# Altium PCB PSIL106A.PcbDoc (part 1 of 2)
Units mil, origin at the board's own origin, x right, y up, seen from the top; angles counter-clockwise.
Board outline 4000 x 3327 mil, 2 copper layers (Top Layer, Bottom Layer), stack 62 mil thick; 63 components, 23 nets, 108 pads, 247 vias.
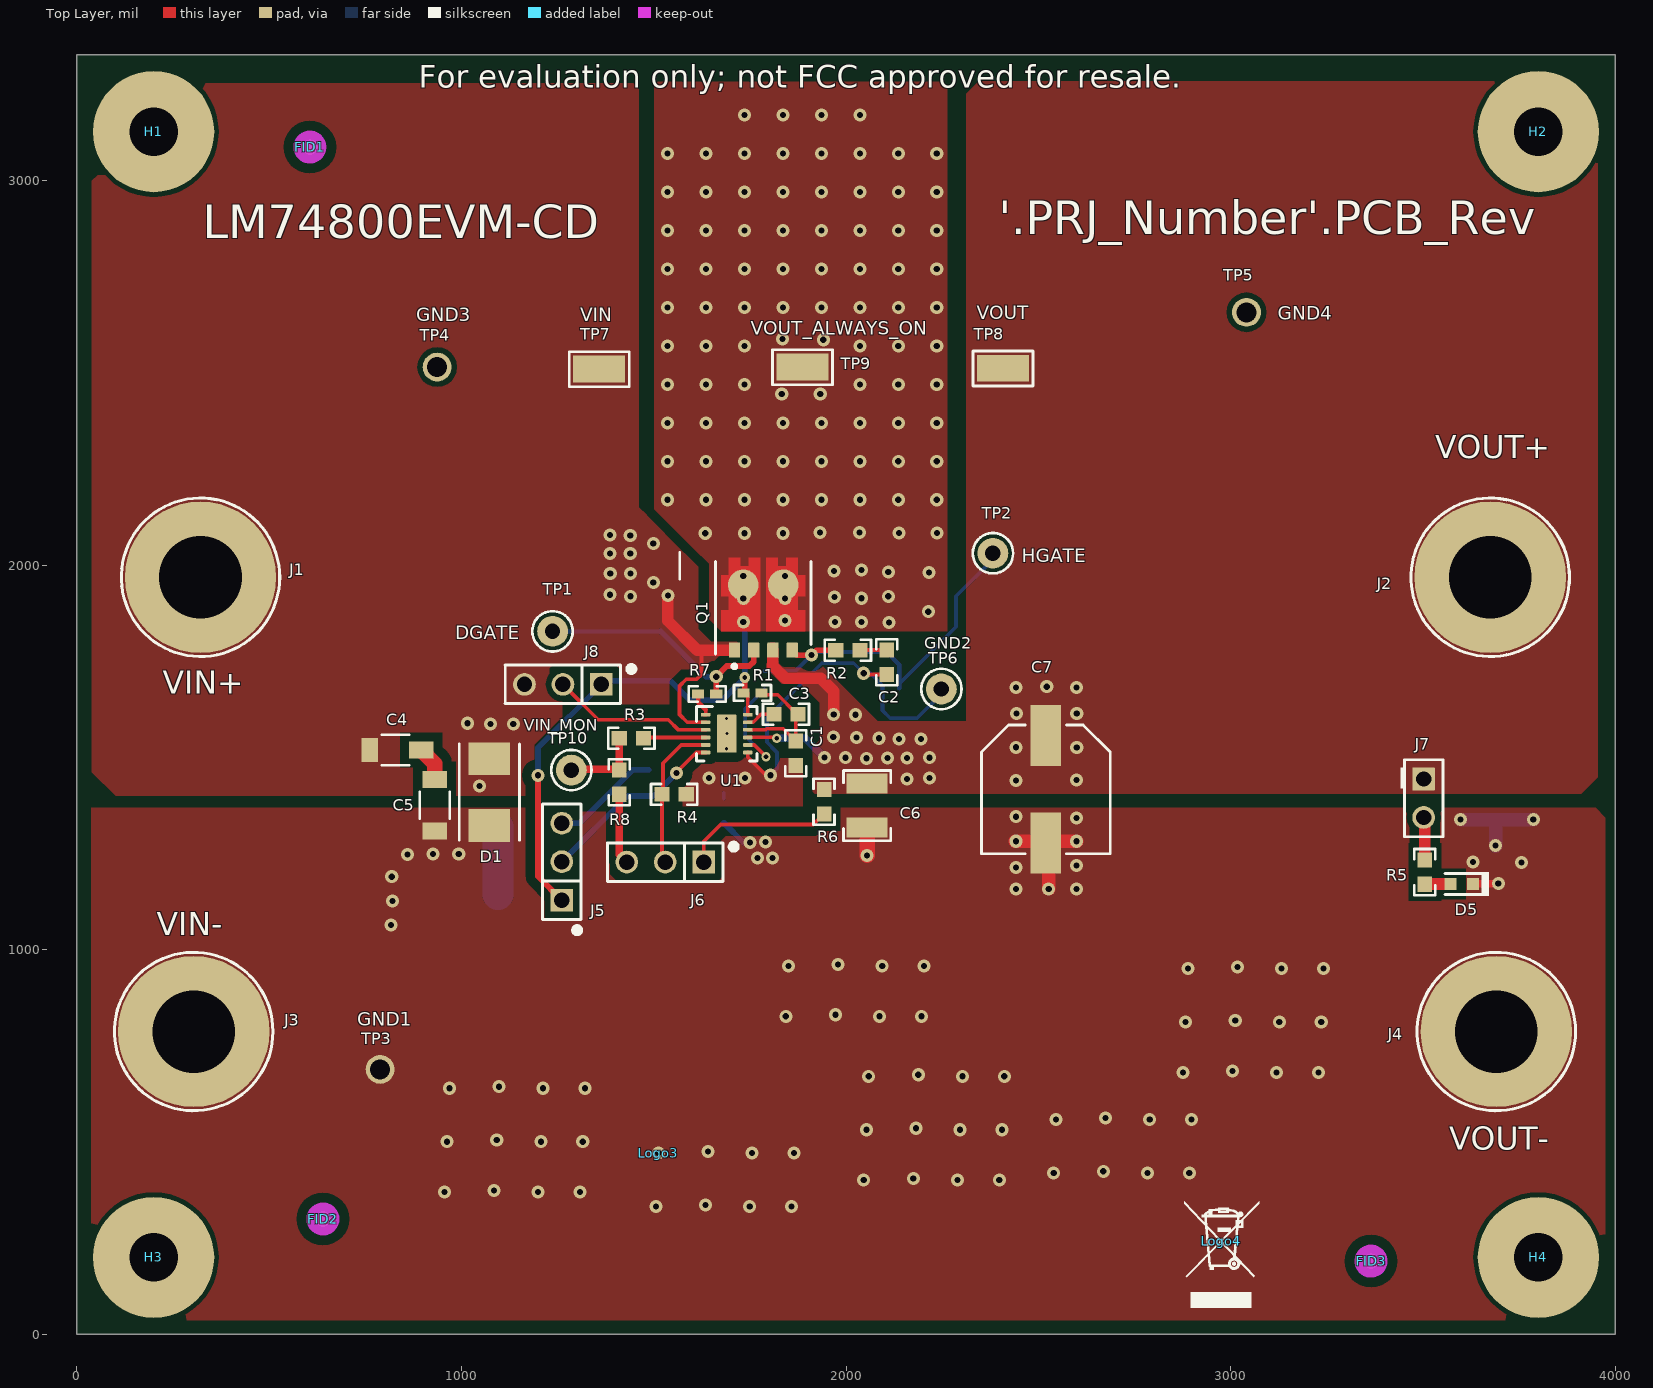
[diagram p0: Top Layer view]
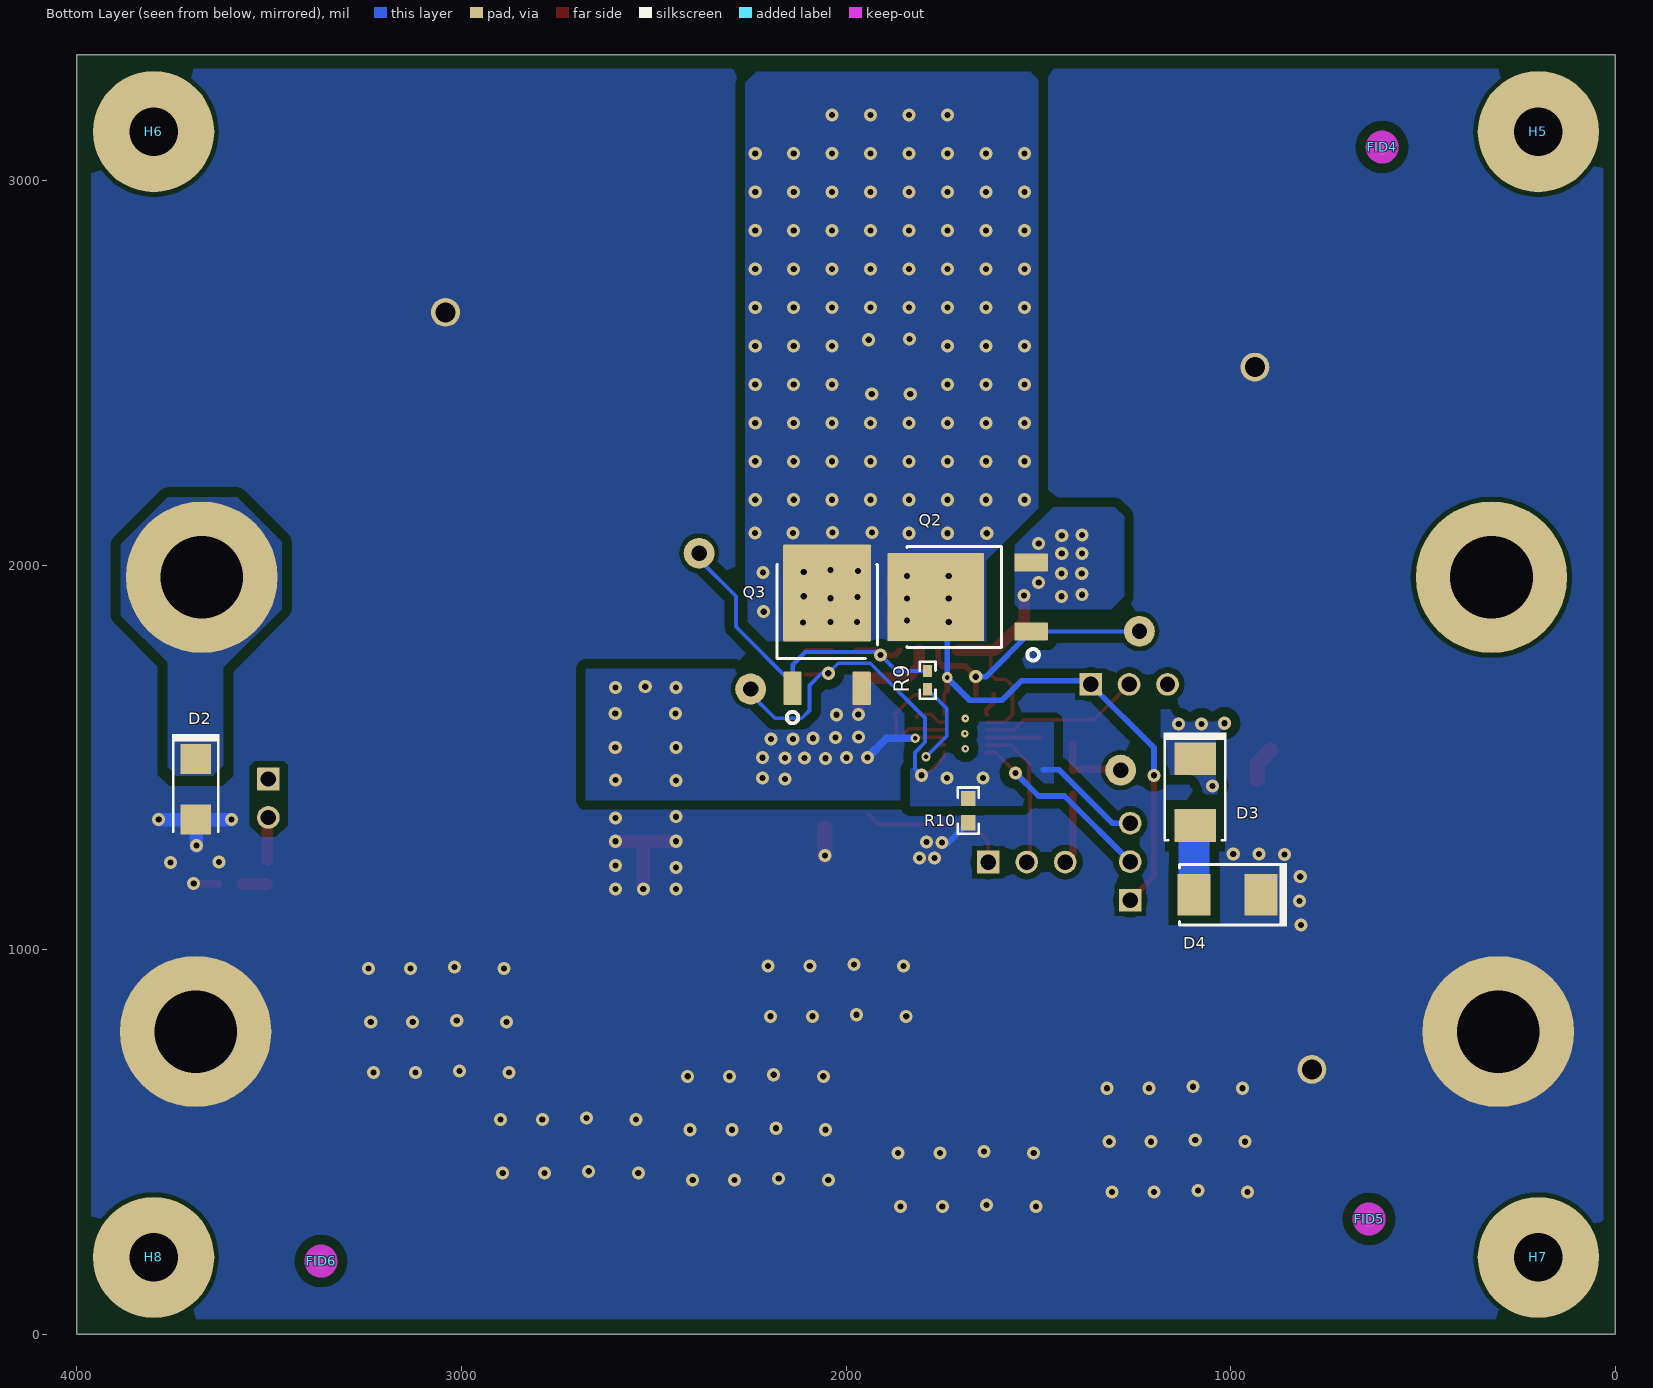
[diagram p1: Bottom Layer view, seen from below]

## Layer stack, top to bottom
Top Solder: solder mask 0.4, Solder Resist, Dk 3.5
Top Layer: signal copper 1.4
Dielectric1: core 59.2, FR-4 High Tg, Dk 4.8
Bottom Layer: signal copper 1.4
Bottom Solder: solder mask 0.4, Solder Resist, Dk 3.5

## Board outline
0,0 0,3327 4000,3327 4000,0

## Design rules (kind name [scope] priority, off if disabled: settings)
AcuteAngle [All] p1: minimum=4.50000000000000E+0001 checktracksonly=FALSE
AssemblyTestPointUsage [All] p1: valid=2
BoardOutlineClearance BoardOutlineClearance_MountingHoles [OnCopper and InComponentClass('Mounting Holes')] p1: gap=39.37 ignorepadtopadclearanceinfootprint=FALSE
BoardOutlineClearance BoardOutlineClearance_Poly [OnCopper and IsPoly] p2: gap=25 ignorepadtopadclearanceinfootprint=FALSE
BoardOutlineClearance [OnCopper and Not InComponentClass('Logo') and not InComponentClass('FiducialMark') and not InRegion(1000,500,4000,800) and not InPoly] p3: gap=75 ignorepadtopadclearanceinfootprint=FALSE
Clearance Clearance_Keepouts [((IsTrack Or IsArc) And Not InPoly) And IsFree and IsKeepOut vs ((IsTrack Or IsArc) And Not InPoly) And IsFree and IsKeepOut] p1: gap=0 ignorepadtopadclearanceinfootprint=FALSE
Clearance Clearance_Poly [InPolygon] p2: gap=25 ignorepadtopadclearanceinfootprint=TRUE except(12: THPad-Fill THPad-Poly THPad-Region)
Clearance Clearance_FiducialMark [IsKeepOut and InComponentClass('FiducialMark') vs IsPad and InComponentClass('FiducialMark')] p3: gap=0 ignorepadtopadclearanceinfootprint=FALSE
Clearance [All] p4: gap=8 ignorepadtopadclearanceinfootprint=TRUE except(20: Fill-Fill Fill-Poly Fill-Region Poly-Poly Poly-Region Region-Region)
ComponentClearance ComponentClearance_MountingHoles_FiducialMarks [InComponentClass('Mounting Holes') vs InComponentClass('FiducialMark')] p1: gap=50 collisioncheckmode=3 verticalgap=10 showdistances=FALSE
ComponentClearance ComponentClearance_Shunt [InComponentClass('Header') vs InComponentClass('Shunt')] p2: gap=0 collisioncheckmode=3 verticalgap=0 showdistances=FALSE
ComponentClearance ComponentClearance_Logo [InComponentClass('Logo')] p3: gap=50 collisioncheckmode=3 verticalgap=10 showdistances=FALSE
ComponentClearance ComponentClearance_ScrewToNut [(HasFootprint('NY PMS 440 0025 PH')) vs (HasFootprint('Keystone_1902C'))] p4: gap=5 collisioncheckmode=3 verticalgap=10 showdistances=FALSE
ComponentClearance ComponentClearance_MountingHoles [InComponentClass('Mounting Holes')] p5: gap=250 collisioncheckmode=3 verticalgap=100000 showdistances=FALSE
ComponentClearance ComponentClearance_SmallPassives [HasFootprint('0201*') or HasFootprint('0402*') or HasFootprint('0508') or HasFootprint('0603*') or HasFootprint('0612') or HasFootprint('0805*') or HasFootprint('0815*') or HasFootprint('0830*') or HasFootprint('1206*') or HasFootprint('1210*') or HasFootprint('1808*') or HasFootprint('1812*') or HasFootprint('1825*') or HasFootprint('2010*') or HasFootprint('2220*') or HasFootprint('2225*') or HasFootprint('2512*') or HasFootprint('2728*') or HasFootprint('3518*') vs HasFootprint('0201*') or HasFootprint('0402*') or HasFootprint('0508') or HasFootprint('0603*') or HasFootprint('0612') or HasFootprint('0805*') or HasFootprint('0815*') or HasFootprint('0830*') or HasFootprint('1206*') or HasFootprint('1210*') or HasFootprint('1808*') or HasFootprint('1812*') or HasFootprint('1825*') or HasFootprint('2010*') or HasFootprint('2220*') or HasFootprint('2225*') or HasFootprint('2512*') or HasFootprint('2728*') or HasFootprint('3518*')] p6: gap=14.96 collisioncheckmode=3 verticalgap=10 showdistances=FALSE
ComponentClearance ComponentClearance_THtoSMT [IsThruComponent vs IsSMTComponent] p7: gap=40 collisioncheckmode=3 verticalgap=30 showdistances=FALSE
ComponentClearance ComponentClearance_THtoTH [IsThruComponent vs IsThruComponent] p8: gap=30 collisioncheckmode=3 verticalgap=30 showdistances=FALSE
ComponentClearance [All] p9: gap=30 collisioncheckmode=3 verticalgap=10 showdistances=FALSE
DiffPairsRouting [All] p1: maxlimit=100 minlimit=10 mostfreqgap=10 toplayer_minwidth=15 toplayer_maxwidth=15 toplayer_prefwidth=15 bottomlayer_minwidth=15 bottomlayer_maxwidth=15 bottomlayer_prefwidth=15 substack1={53B530E0-F7B8-43D4-88A3-5FD2656F86AF} toplayer_{53b530e0-f7b8-43d4-88a3-5fd2656f86af}_minwidth=15 toplayer_{53b530e0-f7b8-43d4-88a3-5fd2656f86af}_maxwidth=15 toplayer_{53b530e0-f7b8-43d4-88a3-5fd2656f86af}_prefwidth=15 bottomlayer_{53b530e0-f7b8-43d4-88a3-5fd2656f86af}_minwidth=15 bottomlayer_{53b530e0-f7b8-43d4-88a3-5fd2656f86af}_maxwidth=15 bottomlayer_{53b530e0-f7b8-43d4-88a3-5fd2656f86af}_prefwidth=15 maxuncoupledlength=1000
FabricationTestPointUsage TestPointUsage [All] p1: valid=2 allowmultiple=FALSE
FabricationTestpoint Testpoint [All] p1: side=3 testpointundercomponent=TRUE minsize=40 maxsize=100 preferedsize=60 minholesize=0 maxholesize=40 preferedholesize=32 testpointgrid=1 allowsidetop=TRUE allowsidebottom=TRUE usegrid=TRUE gridtolerance=0.01
FanoutControl Fanout_LCC [IsLCC] p1: bgadir=Out bgaviamode=Centered fanoutstyle=Auto fanoutdirection=Alternating viagrid=1 // Fanout_LCC (Default Rule)
FanoutControl Fanout_BGA [IsBGA] p2: bgadir=Out bgaviamode=Centered fanoutstyle=Auto fanoutdirection=Alternating viagrid=1 // Fanout_BGA (Default Rule)
FanoutControl Fanout_Default [All] p4: bgadir=Out bgaviamode=Centered fanoutstyle=Auto fanoutdirection=Alternating viagrid=1 // Fanout_Default (Default Rule)
FanoutControl Fanout_Small [(CompPinCount < 5)] p5: bgadir=Out bgaviamode=Centered fanoutstyle=Auto fanoutdirection=OutThenIn viagrid=1 // Fanout_Small (Default Rule)
HoleSize [All] p1: absolutevalues=TRUE maxlimit=251 minlimit=7.87 maxpercent=80.000 minpercent=20.000
MinimumAnnularRing MinimumAnnularRing_ThermalPadVias [IsVia and InAnyComponent] p1: minimumring=5.91
MinimumAnnularRing [All] p2: minimumring=5
MinimumSolderMaskSliver MinimumSolderMaskSliver_Logo [InComponentClass('Logo') vs InComponentClass('Logo')] p1: minsoldermaskwidth=0.7
MinimumSolderMaskSliver [All] p2: minsoldermaskwidth=3.94
PlaneConnect [All] p1: planeconnectstyle=Direct reliefexpansion=10 reliefentries=4 reliefconductorwidth=10 reliefairgap=10
PolygonConnect [All] p1: connectstyle=Direct reliefconductorwidth=10 reliefentries=4 polygonreliefangle="90 Angle" airgapwidth=10
RoutingVias ThermalPadVias [IsVia and InAnyComponent] p1: holewidth=7.87 width=19.68 viastyle="Through Hole" minholewidth=7.87 minwidth=19.68 maxholewidth=12.99 maxwidth=23.62
RoutingVias [All] p2: holewidth=16 width=34 viastyle="Through Hole" minholewidth=8 minwidth=16 maxholewidth=40 maxwidth=65
ShortCircuit U1 [InPadClass('U1') vs Hole] p1: allowed=TRUE
ShortCircuit [All] p2: allowed=FALSE
SilkToBoardRegionClearance [Not ((IsComment or IsDesignator) And (Hide <> 'False')) and not InRegion(1000,500,4000,800)] p1:
SilkToSilkClearance SilkToSilkClearance_Pb-FreeLogo [(HasFootprint('Pb-Free_Overlay_Medium') OR HasFootprint('Pb-Free_Overlay_Small')) vs (HasFootprint('Pb-Free_Overlay_Medium') OR HasFootprint('Pb-Free_Overlay_Small'))] p1: silktosilkclearance=0
SilkToSilkClearance [All] p2: silktosilkclearance=3.94
SilkToSolderMaskClearance SilkToComponentPadClearance [(IsPad or IsFill or IsRegion) and InAnycomponent] p1: minsilkscreentomaskgap=2 clearancetoexposedcopper=TRUE
SilkToSolderMaskClearance "Silk to Solder Mask Opening" [All] p2: minsilkscreentomaskgap=2 clearancetoexposedcopper=FALSE
SolderMaskExpansion SolderMaskExpansion_via [IsVia] p1: expansion=0 istentingtop=FALSE
SolderMaskExpansion SolderMaskExpansion_pads [ispad] p2: expansion=1.97 istentingtop=FALSE
UnRoutedNet [All] p1: checkbadconnections=TRUE
Width [All] p1: maxlimit=100 minlimit=6 preferedwidth=10 substack1={53B530E0-F7B8-43D4-88A3-5FD2656F86AF} checkconnectedcopper=TRUE
13 further rules are at their usual default settings.

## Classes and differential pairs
pad class U1: U1-13
component class PSIL106A: C1 C2 C3 C4 C5 C6 C7 C50 D1 D2 D3 D4 D5 J1 J2 J3 J4 J5 J6 J7 J8 Q1 Q2 Q3 R1 R2 R3 R4 R5 R6 R7 R8 R9 R10 TP1 TP2 TP3 TP4 TP5 TP6 TP7 TP8 TP9 TP10 U1
component class Header: J5 J6 J7 J8
component class "Mounting Holes": H1 H2 H3 H4
component class PSIL106A_HW: FID1 FID2 FID3 FID4 FID5 FID6 H1 H2 H3 H4 H5 H6 H7 H8 Logo3 Logo4 ZZ1 ZZ2 ZZ3
component class FiducialMark: FID1 FID2 FID3 FID4 FID5 FID6
component class AssemblyNote: ZZ1 ZZ2 ZZ3

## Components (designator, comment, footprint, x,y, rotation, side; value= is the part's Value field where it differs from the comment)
C1 "GRM188R72A104KA35J" 0603 1869,1511 r270 top value=0.1uF
C2 "CGA3E2X7R2A103K080AA" 0603 2106,1747.62 r270 top value=0.01uF
C3 "CGA3E2X7R1E104K080AA" 0603 1844,1612 r0 top value=0.1uF
C4 "CGA5L2X7R2A104K160AA" 1206_180#1 828.7,1519.29 r0 top value=0.1uF
C5 "CGA5L2X7R2A104K160AA" 1206_180#2 930.64,1375.93 r270 top value=0.1uF
C6 "CMP-0009084-1" 1210_210 2055,1375 r270 top value=2.2uF
C7 "EEE-FK1J470P" SM_RADIAL_F 2519.68,1417.32 r270 top value=47uF
D1 "SMBJ33CA-13-F" SMB-Bi 1072.83,1409.99 r90 top value=33V
D2 "B170-13-F" SMA 3690.94,1417.32 r270 bottom value=70V
D3 "CMP-0005583-3" SMB 1092.51,1409.99 r270 bottom value=58V
D4 "CMP-0005557-4" SMB 1008,1143 r0 bottom value=24V
D5 "LTST-C190GKT" LED_LTST-C190 3601,1171 r0 top value=Green
FID1 "Fiducial" Fiducial10-20 606,3087 r0 top
FID2 "Fiducial" Fiducial10-20 640,300 r0 top
FID3 "Fiducial" Fiducial10-20 3365,190.39 r0 top
FID4 "Fiducial" Fiducial10-20 606,3087 r180 bottom
FID5 "Fiducial" Fiducial10-20 640,300 r180 bottom
FID6 "Fiducial" Fiducial10-20 3365,190.39 r180 bottom
H1 "NY PMS 440 0025 PH" "NY PMS 440 0025 PH" 200,3127 r0 top locked
H2 "NY PMS 440 0025 PH" "NY PMS 440 0025 PH" 3800,3127 r0 top locked
H3 "NY PMS 440 0025 PH" "NY PMS 440 0025 PH" 200,200 r0 top locked
H4 "NY PMS 440 0025 PH" "NY PMS 440 0025 PH" 3800,200 r0 top locked
H5 "CMP-0003610-1" Keystone_1902C 200,3127 r180 bottom locked
H6 "CMP-0003610-1" Keystone_1902C 3800,3127 r180 bottom locked
H7 "CMP-0003610-1" Keystone_1902C 200,200 r180 bottom locked
H8 "CMP-0003610-1" Keystone_1902C 3800,200 r180 bottom locked
J1 "CMP-0055166-2" Keystone575-8 321.71,1968.5 r90 top locked
J2 "CMP-0055166-2" Keystone575-8 3674.94,1968.5 r90 top locked
J3 "CMP-0055166-2" Keystone575-8 304,787.4 r90 top locked
J4 "CMP-0055166-2" Keystone575-8 3690.94,787.4 r90 top
J5 "PEC03SAAN" CONN_PEC03SAAN 1261,1229 r90 top
J6 "PEC03SAAN" CONN_PEC03SAAN 1530,1228 r180 top
J7 "PEC02SAAN" CONN_PEC02SAAN 3502,1394 r270 top
J8 "PEC03SAAN" CONN_PEC03SAAN 1264,1690 r180 top
Logo3 "FCC disclaimer" FCC_disclaimer 1512,471.38 r0 top
Logo4 "WEEE logo" WEEE_Minimum 2975,242 r0 top
Q1 "NVMFD5C672NLT1G" FP-NVMFD5C672NLT1G_DFN8_5X6-MFG 1785,1889 r0 top
Q2 "IPD100N06S4-03" FP-IPD100N06S4-03_PG-TO252-3-MFG 1684,1917 r90 bottom
Q3 "IPD100N06S4-03" FP-IPD100N06S4-03_PG-TO252-3-MFG 2049,1845 r180 bottom
R1 "RK73Z1ETTP" 0402 1757,1668 r180 top value=0
R2 "CRCW0603100RJNEA" 0603 2005,1778.96 r180 top value=100
R3 "CRCW060391K0JNEA" 0603 1442,1550 r0 top value=91k
R4 "CRCW06033K48FKEA" 0603 1553,1404 r180 top value=3.48k
R5 "CRCW060312K0JNEA" 0603 3505,1202 r90 top value=12k
R6 "CRCW0603100KFKEA" 0603 1943,1384.94 r90 top value=100k
R7 "ERJ-2GE0R00X" 0402 1639,1665 r0 top value=0
R8 "CRCW06039K10JNEA" 0603 1410.5,1435.68 r270 top value=9.1k
R9 "ERJ-2GE0R00X" 0402 1787.99,1701 r90 bottom value=0
R10 "ERJ-3GEY0R00V" 0603 1682,1361.78 r90 bottom value=0
TP1 "5003" Keystone5003 1237,1828 r0 top
TP2 "5003" Keystone5003 2382,2031 r0 top
TP3 "CMP-0055161-1" CONN_1040 788.77,688.98 r0 top
TP4 "CMP-0055161-1" CONN_1040 937,2515 r90 top
TP5 "CMP-0055161-1" CONN_1040 3041.34,2657.48 r90 top
TP6 "5001" Keystone5001 2248,1678 r180 top
TP7 "5015" Testpoint_Keystone_Miniature 1358.27,2509.84 r0 top
TP8 "5015" Testpoint_Keystone_Miniature 2408,2512 r0 top
TP9 "5015" Testpoint_Keystone_Miniature 1887,2515 r0 top
TP10 "5000" Keystone5000 1286,1467.17 r90 top
U1 "PLM74800DRRRQ1" DRR0012E 1689.76,1562.01 r0 top
ZZ1 "These assemblies are ESD sensitive, ESD precautions shall be observed." AssemblyNote 185,3829.11 r0 top
ZZ2 "These assemblies must be clean and free from flux and all contaminants. Use of no clean flux is not acceptable." AssemblyNote 185,3740.56 r0 top
ZZ3 "These assemblies must comply with workmanship standards IPC-A-610 Class 2, unless otherwise specified." AssemblyNote 185,3652 r0 top

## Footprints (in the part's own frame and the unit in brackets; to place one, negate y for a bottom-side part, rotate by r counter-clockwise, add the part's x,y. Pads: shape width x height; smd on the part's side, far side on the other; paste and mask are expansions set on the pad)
0402 [mm] "0402 from SM-752 data"
  rect 0.8x0.6 smd: 1(-0.6,0) 2(0.6,0)
  silkscreen extent -1.22,-0.52 1.22,0.52, body extent -0.55,-0.3 0.55,0.3, height 0.6
0603 [mm] "0603 from SM-752 data"
  rect 1x0.95 smd: 1(-0.8,0) 2(0.8,0)
  silkscreen extent -1.52,-0.69 1.52,0.69, body extent -0.87,-0.47 0.87,0.47, height 1
1206_180#1 [mm] "1206_180"
  rect 1.1x1.6 smd: 1(-1.7,0)
  rect 1.6x1.1 smd: 2(1.7,0)
  silkscreen extent -0.9,-1 0.9,1, body extent -1.75,-0.95 1.75,0.95, height 1.8
1206_180#2 [mm] "1206_180"
  rect 1.1x1.6 smd: 1(-1.7,0) 2(1.7,0)
  silkscreen extent -0.9,-1 0.9,1, body extent -1.75,-0.95 1.75,0.95, height 1.8
1210_210 [mm] "1210"
  rect 1.3x2.7 smd: 1(-1.45,0) 2(1.45,0)
  silkscreen extent -2.32,-1.57 2.32,1.57, body extent -1.7,-1.35 1.7,1.35, height 2.1
AssemblyNote [mil] "Assembly Note"
CONN_1040 [mil] "Test Point, PC  test point Terminal"
  round 75 hole 52: 1(0,0)
  body extent -55,-12 55,13, height 276
CONN_PEC02SAAN [mm] "SULLINS"
  rrect7% 1.5x1.5 hole 1.016: 1(-1.27,0)
  round 1.5 hole 1.016: 2(1.27,0)
  silkscreen extent -2.54,-1.52 2.54,1.27, body extent -2.54,-1.27 2.54,1.27, height 8.38
CONN_PEC03SAAN [mm] "SULLINS"
  rect 1.5x1.5 hole 1.016: 1(-2.54,0)
  round 1.5 hole 1.016: 2(0,0) 3(2.54,0)
  silkscreen extent -4.72,-1.27 3.81,1.27, body extent -3.84,-1.3 3.84,1.3, height 8.38
DRR0012E [mm] "WSON-12"
  rrect40% 0.62x0.25 smd: 1(-1.39,1.25) 2(-1.39,0.75) 3(-1.39,0.25) 4(-1.39,-0.25) 5(-1.39,-0.75) 6(-1.39,-1.25) 7(1.39,-1.25) 8(1.39,-0.75) 9(1.39,-0.25) 10(1.39,0.25) 11(1.39,0.75) 12(1.39,1.25)
  rrect8% 1.3x2.5 smd paste-1.7: 13(0,0)
  silkscreen extent -2,-1.8 2,1.8, body extent -1.5,-1.5 1.5,1.5, height 0.81
FCC_disclaimer [mil]
Fiducial10-20 [mm]
  round 1 smd mask+0.5: 1(0,0)
  Top Layer keep-out circle w1.178: c0,0 r0.5
FP-IPD100N06S4-03_PG-TO252-3-MFG [mm]
  rrect8% 1.2x2.2 smd paste+0 mask+0: 1(-2.28,-4.2) 3(2.28,-4.2)
  rrect2% 5.8x6.4 smd paste+0 mask+0: 4(0,2.1)
  silkscreen extent -3.32,-2.23 3.32,3.99, body extent -3.25,-4.98 3.25,5, height 2.51
FP-NVMFD5C672NLT1G_DFN8_5X6-MFG [mm]
  rrect13% 0.75x1 smd paste+0 mask+0: 1(-1.905,-2.795) 2(-0.635,-2.795) 3(0.635,-2.795) 4(1.905,-2.795)
  round 2.028 smd paste+0 mask+0: 5-6(1.327,1.513) 7-8(-1.327,1.513)
  Top Layer region: -2.28,3.295 -2.28,2.155 -2.775,2.155 -2.775,0.755 -2.28,0.755 -2.28,-0.145 -2.775,-0.145 -2.775,-1.545 -0.2,-1.545 -0.2,3.295 -0.95,3.295 -0.95,2.735 -1.53,2.735 -1.53,3.295
  Top Layer region: 2.28,3.295 2.28,2.155 2.775,2.155 2.775,0.755 2.28,0.755 2.28,-0.145 2.775,-0.145 2.775,-1.545 0.2,-1.545 0.2,3.295 0.95,3.295 0.95,2.735 1.53,2.735 1.53,3.295
  silkscreen extent -3.15,-3.99 3.15,3.05, body extent -2.88,-3.39 2.88,3.39, height 0.25
Keystone575-8 [mm] "Banana Jack"
  round 10 hole 5.45: 1(0,0)
  silkscreen extent -5.23,-5.23 5.23,5.23, body extent -3.92,-3.94 3.95,3.94, height 2.36
Keystone5000 [mil] "For Keystone 500x miniature loop terminals"
  round 80 hole 40: 1(0,0)
  silkscreen extent -52,-52 52,52, body extent -49,-49 49,49, height 182
Keystone5001 [mil] "For Keystone 500x miniature loop terminals"
  round 80 hole 40: 1(0,0)
  silkscreen extent -52,-52 52,52, body extent -49,-49 49,49, height 182
Keystone5003 [mil] "For Keystone 500x miniature loop terminals"
  round 80 hole 40: 1(0,0)
  silkscreen extent -52,-52 52,52, body extent -49,-49 49,49, height 182
Keystone_1902C [mil] "Hex Standoff, 4-40 threaded, nylon"
  round 1 on Mech4: 0(0,0)
  body extent -145,-126 146,126, height 501
LED_LTST-C190 [mm] "Lite-On"
  rect 0.8x0.8 smd: 1(-0.75,0) 2(0.75,0)
  silkscreen extent -1.1,-0.8 1.8,0.8, body extent -0.85,-0.45 0.85,0.45, height 0.9
"NY PMS 440 0025 PH" [mm] "4-40 nylon screw and mounting hole"
  round 8 hole 3.2: 1(0,0)
  body extent -3.3,-3.3 3.3,3.3, height 2.69
SM_RADIAL_F [mm] "8 x 10.2mm:  Panasonic F"
  rect 4x2 smd: 1(-3.55,0) 2(3.55,0)
  silkscreen extent -4.25,-4.25 4.25,4.25, body extent -4.25,-4.25 4.25,4.25, height 10.5
SMA [mm] "Molded Diode, 2-Leads, Body 4.3x2.6mm, IPC Medium Density, based on OnSemi component dimensions and land pattern"
  rect 2x2 smd: 1(-2,0) 2(2,0)
  silkscreen extent -3.66,-1.57 2.79,1.57, body extent -2.6,-1.3 2.6,1.3, height 2.42
SMB [mil] "Molded Diode, 2-Leads, Body 5.4x3.6mm, IPC Medium Density, based on OnSemi component dimensions"
  rect 85x107.99 smd: 1(-87.01,0) 2(87.01,0)
  silkscreen extent -155,-82 125,82, body extent -106,-71 106,71, height 91
SMB-Bi [mil] "Molded Diode, 2-Leads, Body 5.4x3.6mm, IPC Medium Density, based on OnSemi component dimensions"
  rect 85x107.99 smd: 1(-87.01,0) 2(87.01,0)
  silkscreen extent -125,-79 125,79, body extent -104,-73 104,73, height 89
Testpoint_Keystone_Miniature [mil] "Miniature SMT test point"
  rect 135x70 smd: 1(0,0)
  silkscreen extent -78,-46 78,45, body extent -52,-20 52,20, height 61
WEEE_Minimum [mil] "WEEElie bin"
  silkscreen extent -95,-172 99,104

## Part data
C1: library part CMP-0007470-5, "CAP, CERM, 0.1 uF, 100 V, +/- 10%, X7R, 0603", Cap_Case=0603, Manufacturer=MuRata, Supplier Part Number 1=490-6439-1-ND, TempCo=X7R, Tolerance_%=10%, Value1=Unknown, Value2=100V, ValueDisplayed=0.1uF
C2: library part CMP-0007082-4, "CAP, CERM, 0.01 uF, 100 V, +/- 10%, X7R, AEC-Q200 Grade 1, 0603", Cap_Case=0603, Manufacturer=TDK, Supplier Part Number 1=445-5812-1-ND, TempCo=X7R, Tolerance_%=10%, Value1="0.235428 ohm", Value2=100V, ValueDisplayed=0.01uF
C3: library part CMP-0007077-5, "CAP, CERM, 0.1 uF, 25 V, +/- 10%, X7R, AEC-Q200 Grade 1, 0603", Cap_Case=0603, Manufacturer=TDK, Supplier Part Number 1=445-5667-1-ND, TempCo=X7R, Tolerance_%=10%, Value1=Unknown, Value2=25V, ValueDisplayed=0.1uF
C4 C5: library part CMP-0008778-2, "CAP, CERM, 0.1 uF, 100 V, +/- 10%, X7R, AEC-Q200 Grade 1, 1206", Cap_Case=1206_180, Manufacturer=TDK, Supplier Part Number 1=445-5840-1-ND, TempCo=X7R, Tolerance_%=10%, Value1="0.030343 ohm", Value2=100V, ValueDisplayed=0.1uF
C6: "CAP, CERM, 2.2 uF, 100 V, +/- 10%, X7R, 1210", Cap_Case=1210, Manufacturer=Kemet, PartNumber=C1210C225K1RACTU, Supplier Part Number 1=399-5511-2-ND, TempCo=X7R, Tolerance_%=10%, Value1=Unknown, Value2=100V, ValueDisplayed=2.2uF
C7: library part CMP-0011192-2, "CAP, AL, 47 uF, 63 V, +/- 20%, 0.65 ohm, AEC-Q200 Grade 2, SMD", Cap_Case=F, Manufacturer=Panasonic, Supplier Part Number 1=PCE3823CT-ND, Tolerance_%=20%, Value1="0.65 ohm", Value2=63V, ValueDisplayed=47uF
D1: library part CMP-0005564-3, "Diode, TVS, Bi, 33 V, SMB", Manufacturer="Diodes Inc.", Value1=600W
D2: library part CMP-0028391-2, "Diode, Schottky, 70 V, 1 A, SMA", Manufacturer="Diodes Inc.", Value1=1A, Value2=0.79V
D3: "Diode, TVS, Uni, 58 V, 93.6 Vc, SMB", Manufacturer="Diodes Inc.", PartNumber=SMBJ58A-13-F, Value1=600W
D4: "Diode, TVS, Uni, 24 V, 38.9 Vc, SMB", Manufacturer="Diodes Inc.", PartNumber=SMBJ24A-13-F, Value1=600W
D5: library part CMP-0002827-3, "LED, Green, SMD", Color=green, Manufacturer=Lite-On, Power_TotalModule=100mW, Value1=0.1W, Value2=2.1V
FID1 FID2 FID3 FID4 FID5 FID6: library part CMP-0077181-1, "Fiducial mark.  There is nothing to buy or mount.", Manufacturer=N/A
H1 H2 H3 H4: library part CMP-0003617-1, "Machine Screw, Round, #4-40 x 1/4, Nylon, Philips panhead", Manufacturer="B&F Fastener Supply", Supplier Part Number 1=H542-ND
H5 H6 H7 H8: "Standoff, Hex, 0.5\"L #4-40 Nylon", Manufacturer=Keystone, PartNumber=1902C, Supplier Part Number 1=36-1902C-ND
J1 J2 J3 J4: "Standard Banana Jack, Uninsulated, 8.9mm", Manufacturer=Keystone, PartNumber=575-8, Supplier Part Number 1=36-575-8-ND
J5 J6 J8: library part CMP-0002338-1, "Header, 100mil, 3x1, Tin, TH", Color=Black, Current_A=3A, Manufacturer="Sullins Connector Solutions", Supplier Part Number 1=S1012E-03-ND, Voltage_V=1.8kV
J7: library part CMP-0002337-1, "Header, 100mil, 2x1, Tin, TH", Color=Black, Current_A=3A, Manufacturer="Sullins Connector Solutions", Supplier Part Number 1=S1012E-02-ND, Voltage_V=1.8kV
Logo3: library part CMP-0074847-1, "FCC_disclaimer"
Logo4: library part CMP-0074769-1
Q1: library part CMP-0088121-1, "Dual N-Channel MOSFET, 49 A, 60 V, 8-Pin DFN", Manufacturer="ON Semiconductor", PartNumber=NVMFD5C650NL
Q2 Q3: library part CMP-0086637-1, "INF-MOSFET-N-3", Manufacturer=Infineon
R1: library part CMP-0027007-2, "RES, 0, 5%, 0.063 W, AEC-Q200 Grade 0, 0402", Manufacturer="KOA Speer", Power_W=63mW, Supplier Part Number 1=660-RK73Z1ETTP, TempCo=ppm/C, Tolerance_%=5%, Value2=0.063W, Value_Code=0000, ValueDisplayed=0
R2: library part CMP-0025700-4, "RES, 100, 5%, 0.1 W, AEC-Q200 Grade 0, 0603", Manufacturer=Vishay-Dale, Power_W=100mW, Supplier Part Number 1=541-100GCT-ND, TempCo="200 ppm/C", Tolerance_%=5%, Value2=0.1W, Value_Code=100R, ValueDisplayed=100
R3: library part CMP-0025867-4, "RES, 91 k, 5%, 0.1 W, AEC-Q200 Grade 0, 0603", Manufacturer=Vishay-Dale, Power_W=100mW, Supplier Part Number 1=541-91KGCT-ND, TempCo="200 ppm/C", Tolerance_%=5%, Value2=0.1W, Value_Code=91k0, ValueDisplayed=91k
R4: library part CMP-0022377-4, "RES, 3.48 k, 1%, 0.1 W, AEC-Q200 Grade 0, 0603", Manufacturer=Vishay-Dale, Power_W=100mW, Supplier Part Number 1=541-3.48KHCT-ND, TempCo="100 ppm/C", Tolerance_%=1%, Value2=0.1W, Value_Code=3k48, ValueDisplayed=3.48k
R5: library part CMP-0025711-4, "RES, 12 k, 5%, 0.1 W, AEC-Q200 Grade 0, 0603", Manufacturer=Vishay-Dale, Power_W=100mW, Supplier Part Number 1=541-12KGCT-ND, TempCo="200 ppm/C", Tolerance_%=5%, Value2=0.1W, Value_Code=12k0, ValueDisplayed=12k
R6: library part CMP-0021990-4, "RES, 100 k, 1%, 0.1 W, AEC-Q200 Grade 0, 0603", Manufacturer=Vishay-Dale, Power_W=100mW, Supplier Part Number 1=541-100KHCT-ND, TempCo="100 ppm/C", Tolerance_%=1%, Value2=0.1W, Value_Code=100k
R7 R9: library part CMP-0026992-3, "RES, 0, 5%, 0.1 W, AEC-Q200 Grade 0, 0402", Manufacturer=Panasonic, Power_W=100mW, Supplier Part Number 1=P0.0JCT-ND, TempCo="600 ppm/C", Tolerance_%=5%, Value2=0.1W, Value_Code=0000, ValueDisplayed=0
R8: library part CMP-0025869-4, "RES, 9.1 k, 5%, 0.1 W, AEC-Q200 Grade 0, 0603", Manufacturer=Vishay-Dale, Power_W=100mW, Supplier Part Number 1=541-9.1KGCT-ND, TempCo="200 ppm/C", Tolerance_%=5%, Value2=0.1W, Value_Code=9k10, ValueDisplayed=9.1k
R10: library part CMP-0025874-4, "RES, 0, 5%, 0.1 W, AEC-Q200 Grade 0, 0603", Manufacturer=Panasonic, Power_W=100mW, Supplier Part Number 1=P0.0GCT-ND, TempCo="600 ppm/C", Tolerance_%=5%, Value2=0.1W, Value_Code=0000, ValueDisplayed=0
TP1 TP2: library part CMP-0055140-1, "Test Point, Miniature, Orange, TH", Color=Orange, Manufacturer=Keystone, Supplier Part Number 1=36-5003-ND
TP3 TP4 TP5: "TEST POINT SLOTTED .118\", TH", Manufacturer=Keystone, PartNumber=1040, Supplier Part Number 1=36-1040-ND
TP6: library part CMP-0055138-1, "Test Point, Miniature, Black, TH", Color=Black, Manufacturer=Keystone, Supplier Part Number 1=36-5001-ND
TP7 TP8 TP9: "Test Point, Miniature, SMT", Manufacturer=Keystone, Supplier Part Number 1=36-5015TR-ND
TP10: library part CMP-0055137-1, "Test Point, Miniature, Red, TH", Color=Red, Manufacturer=Keystone, Supplier Part Number 1=36-5000-ND
U1: library part CMP-0860384-3, "Ideal Diode Controller with Load Dump Protection, DRR0012E (WSON-12)", Alternate Manufacturer="Texas Instruments"
ZZ1: library part CMP-0077236-1
ZZ2: library part CMP-0077237-1
ZZ3: library part CMP-0077238-1

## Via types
v1: diameter 34, hole 16, Top Layer to Bottom Layer, 241 vias
v2: diameter 19.68, hole 7.87, Top Layer to Bottom Layer, 3 vias
v3: diameter 24, hole 12, Top Layer to Bottom Layer, 2 vias
v4: diameter 28, hole 12, Top Layer to Bottom Layer, 1 vias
